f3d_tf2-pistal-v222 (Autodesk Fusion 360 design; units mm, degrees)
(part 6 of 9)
remove_instance "RemoveInstance27"
move_face "MoveFace158"
move "Move73"
delete_face "DeleteFace95"
move_face "MoveFace159"
move "Move74"
move_face "MoveFace160"
move_face "MoveFace161"
fillet "Fillet136" radius 0.5
move_face "MoveFace162"
chamfer "Chamfer42" distance 12.29
chamfer "Chamfer43" distance 2
chamfer "Chamfer44" distance 2.82
fillet "Fillet137" radius 6.5
extrude "Extrude116" new body of existing geometry blind 18.009
combine "Combine96"
fillet "Fillet138" radius 2.5
fillet "Fillet139" radius 1.75
move_face "MoveFace163"
delete_face "DeleteFace96"
delete_face "DeleteFace97"
delete_face "DeleteFace98"
delete_face "DeleteFace99"
move_face "MoveFace164"
move "Move75"
move_face "MoveFace165"
split "Split44" bodies "Prime_L"
split "Split45" bodies "Prime_top Plate"
move_face "MoveFace166"
delete_face "DeleteFace100"
move_face "MoveFace167" TranslateX 0 TranslateY 0 TranslateZ 1.8
move_face "MoveFace168" TranslateX 0 TranslateY 0 TranslateZ 2
move_face "MoveFace169" TranslateX 0 TranslateY 0 TranslateZ 1
sketch "Sketch117" plane through (0, 14.0955, 0) normal (0, -1, 0) x axis (1, 0, 0)
  curve K1 (-5.7369, 17.551) -> (-5.7369, 17.551)
  circle C1 centre (0, 13.7351) radius 13.2351
  circle C2 centre (0.0126, 17.5506) radius 5.7491
split "Split46" bodies "Trigger Gard_Barrel"
remove_body "RemoveBody61"
delete_face "DeleteFace101"
extrude "Extrude117" cut of existing geometry blind -5
chamfer "Chamfer45" distance 2
chamfer "Chamfer46" distance 1
fillet "Fillet140" radius 44.5
fillet "Fillet141" radius 19
move_face "MoveFace170" TranslateX 0 TranslateY -1 TranslateZ 0
fillet "Fillet142" radius 0.4
fillet "Fillet143" radius 1.5
delete_face "DeleteFace102"
chamfer "Chamfer47" distance 1
chamfer "Chamfer48" distance 1
chamfer "Chamfer49" distance 1
move "Move76" TranslateX 0 TranslateY 0 TranslateZ 4
move_face "MoveFace171" TranslateX 0 TranslateY 0 TranslateZ 4
move_face "MoveFace172" TranslateX 0 TranslateY 0 TranslateZ 4
move_face "MoveFace173" TranslateX 0 TranslateY 0 TranslateZ 1.708
move_face "MoveFace174" TranslateX 0 TranslateY 0 TranslateZ 1.708
sketch "Sketch118" plane through (0, 19.0955, 0) normal (0, -1, 0) x axis (1, 0, 0)
  line L1 (-1.9973, 28) -> (1.9977, 28)
  line L2 (-17.9973, -3.324) -> (-17.9973, 12)
  line L3 (17.9977, -3.324) -> (-17.9973, -3.324)
  line L4 (17.9977, 12) -> (17.9977, -3.324)
  circle C1 centre (0.0126, 17.5506) radius 5.7491
  arc A1 centre (1.9977, 12) radius 16 clockwise from (1.9977, 28) to (17.9977, 12)
  arc A2 centre (-1.9973, 12) radius 16 clockwise from (-17.9973, 12) to (-1.9973, 28)
  circle C2 centre (0.0126, 17.5506) radius 7
  concentric C1 C2
  dimension "d994" diameter C2 = 14
split "Split47"
remove_body "RemoveBody62"
move_face "MoveFace175" TranslateX 0 TranslateY 0 TranslateZ -1
sketch "Sketch119" plane through (0, 19.0955, 0) normal (0, -1, 0) x axis (1, 0, 0)
  line L1 (-1.9973, 28) -> (1.9977, 28)
  line L2 (-17.9973, -3.324) -> (-17.9973, 12)
  line L3 (17.9977, -3.324) -> (-17.9973, -3.324)
  line L4 (17.9977, 12) -> (17.9977, -3.324)
  circle C1 centre (0.0126, 17.5506) radius 7
  arc A1 centre (1.9977, 12) radius 16 clockwise from (1.9977, 28) to (17.9977, 12)
  arc A2 centre (-1.9973, 12) radius 16 clockwise from (-17.9973, 12) to (-1.9973, 28)
  circle C2 centre (0.0126, 17.5506) radius 7
  circle C3 centre (0.0126, 17.5506) radius 10
  concentric C1 C2
  concentric C1 C3
  dimension "d998" diameter C3 = 20
extrude "Extrude118" add sketch "Sketch119" profile of C1 C2 C3 along normal blind 3
chamfer "Chamfer50" distance 2
chamfer "Chamfer51" distance 2
chamfer "Chamfer52" distance 3
chamfer "Chamfer53" distance 5
chamfer "Chamfer54" distance 9
chamfer "Chamfer55" distance 15
chamfer "Chamfer56" distance 25
move "Move77"
move_face "MoveFace176" TranslateX 0 TranslateY -1 TranslateZ 0
offset_faces "OffsetFaces11" distance 3.9
offset_faces "OffsetFaces12" distance -4
delete_face "DeleteFace103"
offset_faces "OffsetFaces13" distance -1.5
move_face "MoveFace177" TranslateX 0 TranslateY 0.9 TranslateZ 0
delete_face "DeleteFace104"
move_face "MoveFace178" TranslateX 0 TranslateY 1 TranslateZ 0
fillet "Fillet144" radius 0.5
move "Move78" TranslateX 0 TranslateY 0 TranslateZ 3
move "Move79"
fillet "Fillet145" radius 1
fillet "Fillet146" radius 5
fillet "Fillet147" radius 1
fillet "Fillet148" radius 1
sketch "Sketch120" plane through (-8.7048, 0, 0) normal (-1, 0, 0) x axis (0, -1, 0)
  line L1 (-243.8387, -10.9055) -> (-247.6684, -10.9055)
  line L2 (-240.3387, -15.9055) -> (-240.3387, -14.4055)
  line L3 (-221.9771, -19.4038) -> (-243.7277, -19.4038)
  line L4 (-218.4255, -25.6041) -> (-218.1133, -24.439)
  line L5 (-212.2404, -31.8982) -> (-213.5959, -31.8982)
  line L6 (-211.0185, -30.2363) -> (-211.277, -31.166)
  line L7 (-212.1595, -28.1797) -> (-211.21, -29.3328)
  line L8 (-211.3292, -23.5455) -> (-212.352, -27.2799)
  line L9 (-247.6613, -10.9038) -> (-220.9739, -10.9038)
  line L10 (-219.0873, -25.0216) -> (-211.3818, -27.0863)
  circle C1 centre (-234, -15) radius 2
  arc A1 centre (-247.6684, -14.4055) radius 3.5 clockwise from (-248.5086, -11.0079) to (-247.6684, -10.9055)
  arc A2 centre (-243.8387, -14.4055) radius 3.5 clockwise from (-243.8387, -10.9055) to (-240.3387, -14.4055)
  arc A3 centre (-243.8387, -15.9055) radius 3.5 clockwise from (-240.3387, -15.9055) to (-243.7277, -19.4038)
  arc A4 centre (-221.9771, -23.4038) radius 4 clockwise from (-221.9771, -19.4038) to (-218.1133, -24.439)
  arc A5 centre (-213.5959, -26.8982) radius 5 clockwise from (-213.5959, -31.8982) to (-218.4255, -25.6041)
  arc A6 centre (-212.2404, -30.8982) radius 1 clockwise from (-211.277, -31.166) to (-212.2404, -31.8982)
  arc A7 centre (-211.982, -29.9685) radius 1 clockwise from (-211.21, -29.3328) to (-211.0185, -30.2363)
  arc A8 centre (-211.3876, -27.5441) radius 1 clockwise from (-212.1595, -28.1797) to (-212.352, -27.2799)
  arc A9 centre (-220.9739, -20.9038) radius 10 clockwise from (-220.9739, -10.9038) to (-211.3292, -23.5455)
  arc A10 centre (-247.6613, -14.4038) radius 3.5 clockwise from (-248.5086, -11.0079) to (-247.6613, -10.9038)
  perpendicular L4 L10
split "Split48" bodies "Mag Release_R (1)", "Mag Release_R (2)", "Mag Release_L (1)", "Mag Release_L (2)"
move "Move80"
fillet "Fillet149" radius 6.5
fillet "Fillet150" radius 5.75
combine "Combine97" bodies "Mag Release_R (2)", "Mag Release_R (1)"
combine "Combine98" bodies "Mag Release_L (2)", "Mag Release_L (1)"
fillet "Fillet151" radius 2
move_face "MoveFace179"
move_face "MoveFace180"
sketch "Sketch121" plane through (0, 144.3129, 0) normal (0, -1, 0) x axis (1, 0, 0)
  line L1 (-18.3981, 10) -> (-18.3981, -29.6952)
  line L2 (-19.9977, 10) -> (-18.3981, 10)
  line L3 (-19.9977, -29.2452) -> (-19.9977, 10)
  line L4 (-19.5477, -29.6952) -> (-19.9977, -29.2452)
  line L5 (-18.3981, -29.6952) -> (-19.5477, -29.6952)
  line L6 (18.3981, -29.6952) -> (18.3981, 10)
  line L7 (19.5477, -29.6952) -> (18.3981, -29.6952)
  line L8 (19.9977, -29.2452) -> (19.5477, -29.6952)
  line L9 (19.9977, 10) -> (19.9977, -29.2452)
  line L10 (18.3981, 10) -> (19.9977, 10)
  line L11 (19.9977, -7.3976) -> (-19.9977, -7.3976)
  point P12 (-19.9977, -7.3976)
  point P13 (19.9977, -7.3976)
  coincident L3 P12
  coincident L9 P13
  perpendicular L9 L11
extrude "Extrude119" new body sketch "Sketch121" profile of L1 L3 L4 L5 L6 L7 L8 L9 L11 along normal blind 40
split "Split49" bodies "Trigger Gard_Barrel (1)"
split "Split50" bodies "Trigger Gard_Barrel (3)", "Trigger Gard_Barrel (4)"
combine "Combine99" bodies "Trigger Gard_Barrel (4)"
move_face "MoveFace181"
move_face "MoveFace182"
combine "Combine100"
combine "Combine101" bodies "Trigger Gard_Barrel (3)"
combine "Combine102" bodies "Trigger Gard_Barrel (1)"
extrude "Extrude120" cut of existing geometry blind -0.2
delete_face "DeleteFace105"
delete_face "DeleteFace106"
delete_face "DeleteFace107"
extrude "Extrude121" cut of existing geometry blind -0.2
delete_face "DeleteFace108"
remove_body "RemoveBody63"
remove_body "RemoveBody64"
sketch "Sketch122" plane through (19.9977, 0, 0) normal (1, 0, 0) x axis (0, 1, 0)
  line L1 (104.3129, 10) -> (222.2172, 10)
  line L2 (104.3129, -22.5858) -> (104.3129, 10)
  line L3 (108.2868, -22.5858) -> (104.3129, -22.5858)
  curve K1 (108.2868, -22.5858) -> (115.5438, -25)
  line L4 (121.2561, -25) -> (115.5438, -25)
  curve K2 (140.7874, -29.2452) -> (121.2561, -25)
  line L5 (210.1841, -29.2452) -> (140.7874, -29.2452)
  line L6 (227.5887, -72.0555) -> (210.1841, -29.2452)
  curve K3 (227.8766, -72.7728) -> (227.5887, -72.0555)
  line L7 (240.0468, -84.669) -> (227.8766, -72.7728)
  curve K4 (225.9553, -60.3717) -> (240.0468, -84.669)
  curve K5 (222.2172, -48.7291) -> (225.9553, -60.3717)
  line L8 (222.2172, 10) -> (222.2172, -48.7291)
  line L9 (110, -21) -> (120, -21)
  line L10 (110, -11) -> (110, -21)
  line L11 (120, -11) -> (110, -11)
  line L12 (120, -21) -> (120, -11)
  line L13 (110, -11) -> (120, -21)
  line L14 (120, -11) -> (110, -21)
  point P19 (115, -16)
  horizontal L9
  perpendicular L9 L10
  parallel L9 L11
  parallel L10 L12
  coincident L13 P19
  coincident L14 P19
extrude "Extrude122" cut sketch "Sketch122" profile of L9 L10 L11 L12 against normal blind 70
chamfer "Chamfer57" distance 1
chamfer "Chamfer58" distance 0.5
chamfer "Chamfer59" distance 1
delete_face "DeleteFace109"
chamfer "Chamfer60" distance 0.5
sketch "Sketch123" plane through (-19.9973, 0, 0) normal (-1, 0, 0) x axis (0, -1, 0)
  line L1 (-143.2629, 10) -> (-104.3129, 10)
  line L2 (-143.2629, -29.2452) -> (-143.2629, 10)
  line L3 (-140.7874, -29.2452) -> (-143.2629, -29.2452)
  curve K1 (-140.3243, -28.9762) -> (-140.7874, -29.2452)
  line L4 (-137.502, -28.9762) -> (-140.3243, -28.9762)
  curve K2 (-137.502, -28.9762) -> (-136.5854, -28.7537)
  curve K3 (-136.5854, -28.7537) -> (-123.6009, -24.9502)
  curve K4 (-123.6009, -24.9502) -> (-113.9615, -24.9317)
  curve K5 (-113.9615, -24.9317) -> (-108.2868, -22.5858)
  line L5 (-104.3129, -22.5858) -> (-108.2868, -22.5858)
  line L6 (-104.3129, 10) -> (-104.3129, -22.5858)
  line L7 (-109.5, -20.2071) -> (-109.5, -11.7929)
  line L8 (-110.7929, -21.5) -> (-109.5, -20.2071)
  line L9 (-119.2071, -21.5) -> (-110.7929, -21.5)
  line L10 (-120.5, -20.2071) -> (-119.2071, -21.5)
  line L11 (-120.5, -11.7929) -> (-120.5, -20.2071)
  line L12 (-119.2071, -10.5) -> (-120.5, -11.7929)
  line L13 (-110.7929, -10.5) -> (-119.2071, -10.5)
  line L14 (-109.5, -11.7929) -> (-110.7929, -10.5)
  line L15 (-119, -11) -> (-111, -11)
  line L16 (-110.2929, -11) -> (-119, -11)
  line L17 (-111, -11) -> (-110.2929, -11)
  line L18 (-120, -12) -> (-120, -20)
  line L19 (-120, -20) -> (-120, -12)
  line L20 (-110, -20) -> (-110, -12)
  line L21 (-110, -12) -> (-110, -20)
  line L22 (-119, -21) -> (-111, -21)
  line L23 (-111, -21) -> (-119, -21)
  line L24 (-115, -21) -> (-115, -11)
  line L25 (-110, -16) -> (-120, -16)
  line L26 (-119.9, -11.1) -> (-110.1, -11.1)
  line L27 (-119.9, -20.9) -> (-119.9, -11.1)
  line L28 (-110.1, -20.9) -> (-119.9, -20.9)
  line L29 (-110.1, -11.1) -> (-110.1, -20.9)
  line L30 (-119.9, -20.9) -> (-110.1, -11.1)
  line L31 (-110.1, -20.9) -> (-119.9, -11.1)
  point P30 (-115, -11)
  point P31 (-115, -21)
  point P32 (-120, -16)
  point P33 (-110, -16)
  point P38 (-115, -16)
  point P36 (-119.9, -20.9)
  point P37 (-110.1, -20.9)
  point P35 (-119.9, -11.1)
  midpoint L15 P30
  midpoint L22 P31
  midpoint L19 P32
  midpoint L21 P33
  horizontal L26
  perpendicular L26 L27
  parallel L26 L28
  parallel L27 L29
  coincident L30 P38
  coincident L31 P38
  midpoint L24 P38
  dimension "d1051" distance P36 P37 = 9.8
  dimension "d1052" distance P35 P36 = 9.8
extrude "Extrude123" new body sketch "Sketch123" profile of L8 L10 L12 L14 L24 L25 L26 L27 L28 L29 against normal blind 39.995 bodies "LockPin"
move_face "MoveFace183"
chamfer "Chamfer61" distance 0.5
chamfer "Chamfer62" distance 0.5
move_face "MoveFace184"
move_face "MoveFace185"
move_face "MoveFace186"
chamfer "Chamfer63" distance 0.5
fillet "Fillet152" radius 0.5
fillet "Fillet153" radius 3.5
move_face "MoveFace187"
sketch "Sketch124" plane through (0, 0, 10) normal (0, 0, 1) x axis (-1, 0, 0)
  line L1 (17.9977, -157.3502) -> (17.9977, -232.6902)
  line L2 (13, -157.3502) -> (17.9977, -157.3502)
  line L3 (13, -215.8866) -> (13, -157.3502)
  line L4 (9.005, -215.8866) -> (13, -215.8866)
  line L5 (9.005, -227) -> (9.005, -215.8866)
  line L6 (9.0048, -227) -> (9.005, -227)
  line L7 (9.0048, -233.7413) -> (9.0048, -227)
  line L8 (17.6992, -233.7413) -> (9.0048, -233.7413)
  line L9 (-9.0048, -233.7413) -> (-17.6992, -233.7413)
  line L10 (-9.0048, -227) -> (-9.0048, -233.7413)
  line L11 (-9.005, -227) -> (-9.0048, -227)
  line L12 (-9.005, -215.8866) -> (-9.005, -227)
  line L13 (-13, -215.8866) -> (-9.005, -215.8866)
  line L14 (-13, -157.3502) -> (-13, -215.8866)
  line L15 (-17.9977, -157.3502) -> (-13, -157.3502)
  line L16 (-17.9977, -232.6902) -> (-17.9977, -157.3502)
  line L17 (-17.9977, -215.8866) -> (-13, -215.8866)
  line L18 (17.9977, -215.8866) -> (13, -215.8866)
  arc A1 centre (-453.519, -99.3783) radius 490 clockwise from (17.9977, -232.6902) to (17.6992, -233.7413)
  arc A2 centre (453.519, -99.3783) radius 490 clockwise from (-17.6992, -233.7413) to (-17.9977, -232.6902)
  point P19 (-13, -215.8866)
  point P22 (-13, -215.8866)
  point P23 (-17.9977, -215.8866)
  point P7 (13, -215.8866)
  point P24 (13, -215.8866)
  point P25 (17.9977, -215.8866)
  coincident P19 P22
  coincident L16 P23
  perpendicular L16 L17
  coincident P7 P24
  coincident L1 P25
  perpendicular L1 L18
extrude "Extrude124" add sketch "Sketch124" profile of L1 L2 L3 L14 L15 L16 L17 L18 along normal blind 5
sketch "Sketch125" plane through (0, 0, 15) normal (0, 0, 1) x axis (-1, 0, 0)
  line L1 (17.9977, -215.8866) -> (13, -215.8866)
  line L2 (17.9977, -157.3502) -> (17.9977, -215.8866)
  line L3 (13, -157.3502) -> (17.9977, -157.3502)
  line L4 (13, -215.8866) -> (13, -157.3502)
  line L5 (17.9977, -157.3502) -> (17.9977, -215.8866)
  line L6 (-17.9977, -157.3502) -> (-13, -157.3502)
  line L7 (-17.9977, -215.8866) -> (-17.9977, -157.3502)
  line L8 (-13, -215.8866) -> (-17.9977, -215.8866)
  line L9 (-13, -157.3502) -> (-13, -215.8866)
  line L10 (-19.9977, -222.2172) -> (-19.9977, -104.3129)
  line L11 (19.9977, -143.2629) -> (19.9977, -222.2172)
  line L12 (19.9977, -215.8866) -> (-19.9977, -215.8866)
  line L13 (19.9977, -157.3502) -> (-19.9977, -157.3502)
  point P16 (-19.9977, -215.8866)
  point P17 (19.9977, -215.8866)
  point P18 (-19.9977, -157.3502)
  point P19 (19.9977, -157.3502)
  coincident L10 P16
  coincident L11 P17
  perpendicular L11 L12
  coincident L10 P18
  coincident L11 P19
  perpendicular L11 L13
extrude "Extrude125" add sketch "Sketch125" along normal blind 2
delete_face "DeleteFace110"
delete_face "DeleteFace111"
delete_face "DeleteFace112"
delete_face "DeleteFace113"
move_face "MoveFace188"
sketch "Sketch126" plane through (0, 0, 29) normal (0, 0, 1) x axis (-1, 0, 0)
  line L1 (-9.7981, -202.6682) -> (-9.7981, -70.258)
  line L2 (9.7981, -202.6682) -> (-9.7981, -202.6682)
  line L3 (9.7981, -70.258) -> (9.7981, -202.6682)
  line L4 (-9.7981, -70.258) -> (9.7981, -70.258)
  line L5 (13, -116) -> (-13, -116)
  line L6 (13, -128) -> (13, -116)
  line L7 (-13, -128) -> (13, -128)
  line L8 (-13, -116) -> (-13, -128)
  line L9 (13, -141) -> (-13, -141)
  line L10 (13, -153) -> (13, -141)
  line L11 (-13, -153) -> (13, -153)
  line L12 (-13, -141) -> (-13, -153)
  line L13 (13, -166) -> (-13, -166)
  line L14 (13, -178) -> (13, -166)
  line L15 (-13, -178) -> (13, -178)
  line L16 (-13, -166) -> (-13, -178)
  line L17 (13, -91) -> (-13, -91)
  line L18 (13, -103) -> (13, -91)
  line L19 (-13, -103) -> (13, -103)
  line L20 (-13, -91) -> (-13, -103)
  line L21 (13, -191) -> (-13, -191)
  line L22 (13, -203) -> (13, -191)
  line L23 (-13, -203) -> (13, -203)
  line L24 (-13, -191) -> (-13, -203)
  point P6 (-13, -116)
  point P9 (-13, -128)
  point P10 (-13, -141)
  point P13 (-13, -153)
  point P14 (-13, -166)
  point P17 (-13, -178)
  point P18 (-13, -91)
  point P19 (13, -91)
  point P21 (-13, -103)
  point P22 (-13, -191)
  point P25 (-13, -203)
  horizontal L5
  vertical L6
  horizontal L7
  vertical L8
  horizontal L9
  vertical L10
  horizontal L11
  vertical L12
  horizontal L13
  vertical L14
  horizontal L15
  vertical L16
  horizontal L17
  vertical L18
  horizontal L19
  vertical L20
  horizontal L21
  vertical L22
  horizontal L23
  vertical L24
  dimension "d1066" distance P6 P9 = 12
  dimension "d1067" distance P10 P13 = 12
  dimension "d1068" distance P14 P17 = 12
  dimension "d1069" distance L7 L9 = 13
  dimension "d1070" distance L11 L13 = 13
  dimension "d1071" distance P18 P19 = 26
  dimension "d1072" distance P18 P21 = 12
  dimension "d1073" distance L5 L19 = 13
  dimension "d1074" distance P22 P25 = 12
  dimension "d1075" distance L15 L21 = 13
extrude "Extrude126" new body sketch "Sketch126" profile of L1 L2 L3 L5 L6 L7 L8 L9 L10 L11 L12 L13 L14 L15 L16 L17 L18 L19 L20 L21 L22 L23 L24 against normal blind 2.7
combine "Combine103"
combine "Combine104"
combine "Combine105"
move_face "MoveFace189"
move_face "MoveFace190"
move_face "MoveFace191"
move_face "MoveFace192"
split "Split51" bodies "Prime_R (1)", "Prime_R (2)", "Prime_R (3)", "Prime_R (4)", "Prime_R (5)", "Prime_L (1)", "Prime_L (2)", "Prime_L (3)"
remove_body "RemoveBody65"
remove_body "RemoveBody66"
remove_body "RemoveBody67"
remove_body "RemoveBody68"
remove_body "RemoveBody69"
remove_body "RemoveBody70"
remove_body "RemoveBody71"
remove_body "RemoveBody72"
remove_body "RemoveBody73"
remove_body "RemoveBody74"
remove_body "RemoveBody75"
remove_body "RemoveBody76"
sketch "Sketch127" plane through (0, 202.6683, 0) normal (0, 1, 0) x axis (-1, 0, 0)
  line L1 (12.9294, 26.3) -> (-12.9297, 26.3)
  line L2 (-7.9137, 29) -> (7.9134, 29)
  line L3 (-12.9297, 26.3) -> (12.9294, 26.3)
  line L4 (-9.7981, 22.3) -> (-9.7981, 26.1)
  line L5 (9.7981, 26.1) -> (9.7981, 22.3)
  curve K1 (-4.7222, 26.5873) -> (-8.019, 24.6694)
  curve K2 (8.019, 24.6694) -> (4.7222, 26.5873)
  line L6 (-9.104, 22.8662) -> (-9.7981, 22.8662)
  line L7 (-9.7981, 26.3) -> (-9.7981, 26.1)
  line L8 (9.104, 22.8662) -> (9.7981, 22.8662)
  line L9 (9.7981, 26.3) -> (9.7981, 26.1)
  arc A1 centre (-1.9977, 12) radius 18 clockwise from (-12.9297, 26.3) to (-7.9137, 29)
  arc A2 centre (1.9973, 12) radius 18 clockwise from (7.9134, 29) to (12.9294, 26.3)
  closed curve K3 centre (3.5, 20.7227)
  closed curve K4 centre (-3.5, 20.7227)
  arc A3 centre (-3.5, 20.7227) radius 6.2 clockwise from (-9.3189, 22.8629) to (-6.2082, 26.3)
  arc A4 centre (3.5, 20.7227) radius 6.2 clockwise from (1.8918, 26.7105) to (6.2082, 26.3)
  arc A5 centre (3.5, 20.7227) radius 6.2 clockwise from (6.2082, 26.3) to (9.3177, 22.8662)
  point P22 (-9.7981, 22.8662)
  point P23 (-9.104, 22.8662)
  point P10 (-9.7981, 26.1)
  point P24 (-9.7981, 26.1)
  point P25 (-9.7981, 26.3)
  point P26 (9.7981, 22.8662)
  point P27 (9.104, 22.8662)
  point P13 (9.7981, 26.1)
  point P28 (9.7981, 26.1)
  point P29 (9.7981, 26.3)
  point P31 (-6.2082, 26.3)
  point P19 (-3.5, 20.7227)
  point P30 (-3.5, 20.7227)
  point P34 (6.2082, 26.3)
  point P16 (3.5, 20.7227)
  point P33 (3.5, 20.7227)
  point P37 (9.3177, 22.8662)
  point P36 (3.5, 20.7227)
  coincident L4 P22
  coincident K4 P23
  perpendicular L4 L6
  coincident P10 P24
  coincident L3 P25
  perpendicular L3 L7
  coincident L5 P26
  coincident K3 P27
  perpendicular L5 L8
  coincident P13 P28
  coincident L3 P29
  perpendicular L3 L9
  coincident L3 P31
  coincident P19 P30
  coincident L3 P34
  coincident P16 P33
  coincident L8 P37
  coincident P16 P36
  dimension "d1078" radius A3 = 6.2
  dimension "d1079" radius A4 = 6.2
extrude "Extrude127" new body sketch "Sketch127" profile of L1 L3 L4 L5 L6 L7 L8 L9 A3 A5 against normal blind 132.41
combine "Combine106"
move_face "MoveFace193"
sketch "Sketch128" plane through (0, 70.058, 0) normal (0, 1, 0) x axis (-1, 0, 0)
  line L1 (8.4524, 1) -> (8.4524, 26)
  line L2 (15.2981, 1) -> (8.4524, 1)
  line L3 (15.2981, -14.4738) -> (15.2981, 1)
  line L4 (-7.5981, -22.1738) -> (7.5981, -22.1738)
  line L5 (-15.2981, 1) -> (-15.2981, -14.4738)
  line L6 (-8.4524, 1) -> (-15.2981, 1)
  line L7 (-8.4524, 26) -> (-8.4524, 1)
  line L8 (8.4524, 26) -> (-8.4524, 26)
  line L9 (-19.9977, 10) -> (-19.9977, 12)
  line L10 (-18.3981, 10) -> (-19.9977, 10)
  line L11 (-18.3981, 1) -> (-18.3981, 10)
  line L12 (-15.4981, 1) -> (-18.3981, 1)
  line L13 (-15.4981, -24.564) -> (-15.4981, 1)
  line L14 (-15.4981, -24.564) -> (15.4981, -24.564)
  line L15 (15.4981, 1) -> (15.4981, -24.564)
  line L16 (18.3981, 1) -> (15.4981, 1)
  line L17 (18.3981, 10) -> (18.3981, 1)
  line L18 (19.9973, 10) -> (18.3981, 10)
  line L19 (19.9973, 12) -> (19.9973, 10)
  line L20 (-1.9977, 30) -> (1.9973, 30)
  line L21 (-17.9977, 14) -> (-17.9977, 10)
  line L22 (-17.9977, 10) -> (-17.9977, 14)
  line L23 (-17.9977, 14) -> (-19.9977, 14)
  line L24 (-19.9977, 14) -> (-17.9977, 14)
  line L25 (-19.9977, 10) -> (-19.9973, 10)
  line L26 (-17.9977, 10) -> (-19.9973, 10)
  line L27 (-18.3981, 10) -> (-17.9977, 10)
  line L28 (-19.9977, 10) -> (-18.3981, 10)
  line L29 (17.9977, 14) -> (17.9977, 10)
  line L30 (17.9977, 10) -> (17.9977, 14)
  line L31 (17.9977, 10) -> (18.3981, 10)
  line L32 (19.9973, 10) -> (17.9977, 10)
  line L33 (19.9977, 10) -> (19.9973, 10)
  line L34 (19.9973, 10) -> (19.9977, 10)
  line L35 (18.3981, 10) -> (19.9973, 10)
  line L36 (19.9977, 14) -> (17.9977, 14)
  line L37 (17.9977, 14) -> (19.9977, 14)
  arc A1 centre (7.5981, -14.4738) radius 7.7 clockwise from (15.2981, -14.4738) to (7.5981, -22.1738)
  arc A2 centre (-7.5981, -14.4738) radius 7.7 clockwise from (-7.5981, -22.1738) to (-15.2981, -14.4738)
  arc A3 centre (-1.9977, 12) radius 18 clockwise from (-19.9977, 12) to (-1.9977, 30)
  arc A4 centre (1.9973, 12) radius 18 clockwise from (1.9973, 30) to (19.9973, 12)
extrude "Extrude128" cut sketch "Sketch128" profile of A3 L9 L10 L18 L19 A4 L21 L22 L23 L24 L25 L26 L27 L28 L29 L30 L31 L32 L35 L36 L37 against normal blind 63
sketch "Sketch129" plane through (0, 19.0955, 0) normal (0, -1, 0) x axis (1, 0, 0)
  line L1 (22.3197, 8.4101) -> (20.7973, 8.4101)
  line L2 (22.3197, 12) -> (22.3197, 8.4101)
  line L3 (-1.9973, 32.3224) -> (1.9973, 32.3224)
  line L4 (-22.3197, 8.4101) -> (-22.3197, 12)
  line L5 (-20.7973, 8.4101) -> (-22.3197, 8.4101)
  line L6 (-20.7973, 12) -> (-20.7973, 8.4101)
  line L7 (1.9973, 30.8) -> (-1.9973, 30.8)
  line L8 (20.7973, 8.4101) -> (20.7973, 12)
  line L9 (-18.167, 14) -> (-19.5911, 14)
  line L10 (-17.9977, 12) -> (-17.9977, 14)
  line L11 (-19.7044, 10) -> (-18.3981, 10)
  line L12 (-17.9977, 10) -> (-17.9977, 12)
  line L13 (-17.9977, 10) -> (-18.2902, 10)
  line L14 (-18.3981, 10) -> (-18.2902, 10)
  line L15 (-17.9977, 14) -> (-18.167, 14)
  line L16 (19.5915, 14) -> (18.1673, 14)
  line L17 (18.1673, 14) -> (17.9977, 14)
  line L18 (17.9977, 14) -> (17.9977, 12)
  line L19 (19.8862, 14) -> (19.5915, 14)
  line L20 (17.9977, 14) -> (19.9977, 14)
  line L21 (17.9977, 12) -> (17.9977, 10)
  line L22 (18.2906, 10) -> (17.9977, 10)
  line L23 (18.3981, 10) -> (19.7048, 10)
  line L24 (18.2906, 10) -> (18.3981, 10)
  line L25 (19.9977, 10) -> (19.7048, 10)
  line L26 (-19.5911, 14) -> (-19.8859, 14)
  line L27 (-17.9977, 14) -> (-19.9977, 14)
  line L28 (-21.0977, 13.8) -> (-18.1977, 13.8)
  line L29 (-21.0977, 10.2) -> (-21.0977, 13.8)
  line L30 (-18.1977, 10.2) -> (-21.0977, 10.2)
  line L31 (-18.1977, 13.8) -> (-18.1977, 10.2)
  line L32 (21.0977, 13.8) -> (18.1977, 13.8)
  line L33 (21.0977, 10.2) -> (21.0977, 13.8)
  line L34 (18.1977, 10.2) -> (21.0977, 10.2)
  line L35 (18.1977, 13.8) -> (18.1977, 10.2)
  arc A1 centre (1.9973, 12) radius 20.3224 clockwise from (1.9973, 32.3224) to (22.3197, 12)
  arc A2 centre (-1.9973, 12) radius 20.3224 clockwise from (-22.3197, 12) to (-1.9973, 32.3224)
  arc A3 centre (-1.9973, 12) radius 18.8 clockwise from (-20.7973, 12) to (-1.9973, 30.8)
  arc A4 centre (1.9973, 12) radius 18.8 clockwise from (1.9973, 30.8) to (20.7973, 12)
  horizontal L28
  vertical L29
  horizontal L30
  vertical L31
  horizontal L32
  vertical L33
  horizontal L34
  vertical L35
  dimension "d1084" distance L20 L32 = 0.2
  dimension "d1085" distance L18 L35 = 0.2
  dimension "d1086" distance L22 L34 = 0.2
  dimension "d1087" distance L11 L30 = 0.2
  dimension "d1088" distance L15 L28 = 0.2
  dimension "d1089" distance L10 L31 = 0.2
extrude "Extrude129" new body sketch "Sketch129" profile of L6 A3 A4 L8 L28 L29 L30 L31 L32 L33 L34 L35 against normal blind 204.791
combine "Combine107"
fillet "Fillet154" radius 0.5
move_face "MoveFace194"
move_face "MoveFace195"
sketch "Sketch130" plane through (-18.1977, 0, 0) normal (1, 0, 0) x axis (0, 1, 0)
  line L1 (19.5955, 13.3) -> (228.793, 13.3)
  line L2 (19.5955, 10.7) -> (19.5955, 13.3)
  line L3 (230.6743, 10.7) -> (19.5955, 10.7)
  line L4 (228.793, 13.3) -> (230.6743, 10.7)
  line L5 (227, 10) -> (233.7413, 10)
  line L6 (227, 10) -> (215.8866, 10)
  line L7 (223.8866, 10) -> (223.8866, 17)
  curve K1 (202.6682, 30.2953) -> (228.4312, 13.8)
  line L8 (228.4312, 13.8) -> (228.793, 13.3)
  line L9 (230.6743, 10.7) -> (228.793, 13.3)
  line L10 (230.6743, 10.7) -> (231.0361, 10.2)
  line L11 (226.1158, 17) -> (223.8866, 17)
  line L12 (231.1808, 10) -> (231.0361, 10.2)
  line L13 (224, 10) -> (224, 17)
  point P10 (223.8866, 17)
  point P18 (223.8866, 17)
  point P19 (226.1158, 17)
  point P17 (231.0361, 10.2)
  point P20 (231.0361, 10.2)
  point P21 (231.1808, 10)
  point P22 (224, 17)
  point P23 (224, 10)
  coincident P10 P18
  coincident K1 P19
  perpendicular L7 L11
  coincident P17 P20
  coincident L5 P21
  parallel L10 L12
  coincident L11 P22
  coincident L6 P23
  perpendicular L6 L13
extrude "Extrude130" new body sketch "Sketch130" profile of L1 L3 L5 L6 K1 L8 L10 L11 L12 L13 along normal blind 40 and against normal blind 4
combine "Combine108"
combine "Combine109"
move_face "MoveFace196"
split "Split52" bodies "GripAft_R (1)", "GripAft_L  (1)"
remove_body "RemoveBody77"
remove_body "RemoveBody78"
fillet "Fillet155" radius 0.2
fillet "Fillet156" radius 1.5
move "Move81"
delete_face "DeleteFace114"
delete_face "DeleteFace115"
move "Move82"
move_face "MoveFace197"
fillet "Fillet157" radius 0.2
delete_face "DeleteFace116"
delete_face "DeleteFace117"
fillet "Fillet158" radius 0.5
fillet "Fillet159" radius 1.25
move_face "MoveFace198"
move_face "MoveFace199"
chamfer "Chamfer64" distance 1
move_face "MoveFace200"
chamfer "Chamfer65" distance 1.314
fillet "Fillet160" radius 28.25
combine "Combine110"
sketch "Sketch131" plane through (0, 146.2975, 39.2504) normal (0, 0.9658, 0.2591) x axis (-1, 0, 0)
  line L1 (-9.9977, -113.0105) -> (-9.9977, -106.1973)
  curve K1 (-4.9977, -118.0121) -> (-9.9977, -113.0105)
  line L2 (4.9977, -118.0121) -> (-4.9977, -118.0121)
  curve K2 (9.9977, -113.0105) -> (4.9977, -118.0121)
  line L3 (9.9977, -106.1973) -> (9.9977, -113.0105)
  line L4 (-7.9977, -104.1972) -> (7.9977, -104.1972)
  line L5 (-5.6, -107.2) -> (5.6, -107.2)
  line L6 (-5.6, -101.1945) -> (-5.6, -107.2)
  line L7 (5.6, -101.1945) -> (-5.6, -101.1945)
  line L8 (5.6, -107.2) -> (5.6, -101.1945)
  line L9 (-5.6, -101.1945) -> (5.6, -107.2)
  line L10 (5.6, -101.1945) -> (-5.6, -107.2)
  closed curve K3 centre (-7.9977, -106.1973)
  closed curve K4 centre (7.9977, -106.1973)
  point P16 (0, -104.1972)
  horizontal L5
  perpendicular L5 L6
  parallel L5 L7
  parallel L6 L8
  coincident L9 P16
  coincident L10 P16
  midpoint L4 P16
extrude "Extrude131" add sketch "Sketch131" profile of L4 L5 L6 L8 along normal blind 2.428
delete_face "DeleteFace118"
delete_face "DeleteFace119"
chamfer "Chamfer66" distance 1.598
delete_face "DeleteFace120"
fillet "Fillet161" radius 2
fillet "Fillet162" radius 2
move_face "MoveFace201"
move_face "MoveFace202"
combine "Combine111"
offset_faces "OffsetFaces14" distance -0.3
delete_face "DeleteFace121"
delete_face "DeleteFace122"
move_face "MoveFace203"
move_face "MoveFace204"
chamfer "Chamfer67" distance 0.3
delete_face "DeleteFace123"
delete_face "DeleteFace124"
delete_face "DeleteFace125"
delete_face "DeleteFace126"
chamfer "Chamfer68" distance 0.5
offset_faces "OffsetFaces15" distance 0.75
sketch "Sketch132" plane through (0, 0, 26.3) normal (0, 0, -1) x axis (1, 0, 0)
  line L1 (-6.2082, -216.6683) -> (-6.2082, -70.2583)
  line L2 (6.2082, -216.6683) -> (-6.2082, -216.6683)
  line L3 (6.2082, -70.2583) -> (6.2082, -216.6683)
  line L4 (9.7981, -70.2583) -> (6.2082, -70.2583)
  line L5 (9.7981, -70.258) -> (9.7981, -70.2583)
  line L6 (-9.7981, -70.258) -> (9.7981, -70.258)
  line L7 (-9.7981, -70.2583) -> (-9.7981, -70.258)
  line L8 (-6.2082, -70.2583) -> (-9.7981, -70.2583)
  circle C1 centre (-0.0006, -177.3741) radius 1.5
  circle C2 centre (0.0406, -189.4201) radius 1.5
  circle C3 centre (0.0406, -189.4201) radius 1.5
  circle C4 centre (0.0406, -189.4201) radius 1.5
extrude "Extrude132" cut sketch "Sketch132" profile of C1 C2 C3 C4 against normal blind 10
chamfer "Chamfer69" distance 1.6
sketch "Sketch133" plane through (12.7981, 0, 0) normal (1, 0, 0) x axis (0, 1, 0)
  line L1 (178.2, 26.3997) -> (190.8, 26.3997)
  line L2 (178.2, 26.1) -> (178.2, 26.3997)
  line L3 (165.8, 26.1) -> (178.2, 26.1)
  line L4 (165.8, 26.3997) -> (165.8, 26.1)
  line L5 (153.2, 26.3997) -> (165.8, 26.3997)
  line L6 (153.2, 26.1) -> (153.2, 26.3997)
  line L7 (140.8, 26.1) -> (153.2, 26.1)
  line L8 (140.8, 26.3997) -> (140.8, 26.1)
  line L9 (128.2, 26.3997) -> (140.8, 26.3997)
  line L10 (128.2, 26.1) -> (128.2, 26.3997)
  line L11 (115.8, 26.1) -> (128.2, 26.1)
  line L12 (115.8, 26.3997) -> (115.8, 26.1)
  line L13 (103.2, 26.3997) -> (115.8, 26.3997)
  line L14 (103.2, 26.1) -> (103.2, 26.3997)
  line L15 (90.8, 26.1) -> (103.2, 26.1)
  line L16 (90.8, 26.3997) -> (90.8, 26.1)
  line L17 (72.258, 26.3997) -> (90.8, 26.3997)
  line L18 (72.258, 2.0244) -> (72.258, 26.3997)
  line L19 (80.1147, 2.0244) -> (72.258, 2.0244)
  line L20 (95.9689, 21.6299) -> (86.6444, 21.5887)
  line L21 (98.2082, 21.6343) -> (96.0036, 21.6343)
  line L22 (99.0393, 20.0686) -> (99.0789, 20.5623)
  curve K1 (100.6801, 14.8028) -> (99.0393, 20.0686)
  curve K2 (104.47, 20.0672) -> (102.8265, 14.8022)
  line L23 (104.4307, 20.5609) -> (104.47, 20.0672)
  line L24 (107.5222, 21.6343) -> (105.3176, 21.6343)
  line L25 (108.3533, 20.0686) -> (108.3929, 20.5623)
  curve K3 (109.9941, 14.8028) -> (108.3533, 20.0686)
  curve K4 (113.784, 20.0672) -> (112.1405, 14.8022)
  line L26 (113.7447, 20.5609) -> (113.784, 20.0672)
  line L27 (116.8362, 21.6343) -> (114.6316, 21.6343)
  line L28 (117.6673, 20.0686) -> (117.7069, 20.5623)
  curve K5 (119.3081, 14.8028) -> (117.6673, 20.0686)
  curve K6 (123.098, 20.0672) -> (121.4545, 14.8022)
  line L29 (123.0587, 20.5609) -> (123.098, 20.0672)
  line L30 (126.1502, 21.6343) -> (123.9456, 21.6343)
  line L31 (126.9813, 20.0686) -> (127.0209, 20.5623)
  curve K7 (128.6221, 14.8028) -> (126.9813, 20.0686)
  curve K8 (132.412, 20.0672) -> (130.7685, 14.8022)
  line L32 (132.3727, 20.5609) -> (132.412, 20.0672)
  line L33 (135.4642, 21.6343) -> (133.2596, 21.6343)
  line L34 (136.2953, 20.0686) -> (136.3349, 20.5623)
  curve K9 (137.9361, 14.8028) -> (136.2953, 20.0686)
  curve K10 (141.726, 20.0672) -> (140.0825, 14.8022)
  line L35 (141.6867, 20.5609) -> (141.726, 20.0672)
  line L36 (144.7782, 21.6343) -> (142.5736, 21.6343)
  line L37 (145.6093, 20.0686) -> (145.6489, 20.5623)
  curve K11 (147.2501, 14.8028) -> (145.6093, 20.0686)
  curve K12 (151.04, 20.0672) -> (149.3965, 14.8022)
  line L38 (151.0007, 20.5609) -> (151.04, 20.0672)
  line L39 (154.0922, 21.6343) -> (151.8876, 21.6343)
  line L40 (154.9233, 20.0686) -> (154.9629, 20.5623)
  curve K13 (156.5641, 14.8028) -> (154.9233, 20.0686)
  curve K14 (160.354, 20.0672) -> (158.7105, 14.8022)
  line L41 (160.3147, 20.5609) -> (160.354, 20.0672)
  line L42 (163.4062, 21.6343) -> (161.2016, 21.6343)
  line L43 (164.2373, 20.0686) -> (164.2769, 20.5623)
  curve K15 (165.8781, 14.8028) -> (164.2373, 20.0686)
  curve K16 (169.668, 20.0672) -> (168.0245, 14.8022)
  line L44 (169.6287, 20.5609) -> (169.668, 20.0672)
  line L45 (172.7202, 21.6343) -> (170.5156, 21.6343)
  line L46 (173.5513, 20.0686) -> (173.5909, 20.5623)
  curve K17 (175.1921, 14.8028) -> (173.5513, 20.0686)
  curve K18 (178.982, 20.0672) -> (177.3385, 14.8022)
  line L47 (178.9427, 20.5609) -> (178.982, 20.0672)
  line L48 (182.0342, 21.6343) -> (179.8296, 21.6343)
  line L49 (182.8653, 20.0686) -> (182.9049, 20.5623)
  curve K19 (184.5061, 14.8028) -> (182.8653, 20.0686)
  curve K20 (188.296, 20.0672) -> (186.6525, 14.8022)
  line L50 (188.2567, 20.5609) -> (188.296, 20.0672)
  line L51 (189.1436, 22.3) -> (188.5441, 21.3452)
  line L52 (216.6682, 22.3) -> (189.1436, 22.3)
  line L53 (216.6682, 26.1) -> (216.6682, 22.3)
  line L54 (190.8, 26.1) -> (216.6682, 26.1)
  line L55 (190.8, 26.3997) -> (190.8, 26.1)
  line L56 (77.1329, 14.212) -> (82.8671, 14.212)
  line L57 (77.1329, 23.788) -> (77.1329, 14.212)
  line L58 (82.8671, 23.788) -> (77.1329, 23.788)
  line L59 (82.8671, 14.212) -> (82.8671, 23.788)
  line L60 (77.1329, 23.788) -> (82.8671, 14.212)
  line L61 (82.8671, 23.788) -> (77.1329, 14.212)
  arc A1 centre (121.5101, -0.9197) radius 41.5 clockwise from (80.1147, 2.0244) to (86.6444, 21.5887)
  arc A2 centre (96.1135, 20.6404) radius 1 clockwise from (95.9689, 21.6299) to (96.0036, 21.6343)
  arc A3 centre (98.0821, 20.6423) radius 1 clockwise from (98.2082, 21.6343) to (99.0789, 20.5623)
  arc A4 centre (101.7635, 53.7877) radius 39 clockwise from (102.8265, 14.8022) to (100.6801, 14.8028)
  arc A5 centre (105.4275, 20.6404) radius 1 clockwise from (104.4307, 20.5609) to (105.3176, 21.6343)
  arc A6 centre (107.3961, 20.6423) radius 1 clockwise from (107.5222, 21.6343) to (108.3929, 20.5623)
  arc A7 centre (111.0775, 53.7877) radius 39 clockwise from (112.1405, 14.8022) to (109.9941, 14.8028)
  arc A8 centre (114.7415, 20.6404) radius 1 clockwise from (113.7447, 20.5609) to (114.6316, 21.6343)
  arc A9 centre (116.7101, 20.6423) radius 1 clockwise from (116.8362, 21.6343) to (117.7069, 20.5623)
  arc A10 centre (120.3915, 53.7877) radius 39 clockwise from (121.4545, 14.8022) to (119.3081, 14.8028)
  arc A11 centre (124.0555, 20.6404) radius 1 clockwise from (123.0587, 20.5609) to (123.9456, 21.6343)
  arc A12 centre (126.0241, 20.6423) radius 1 clockwise from (126.1502, 21.6343) to (127.0209, 20.5623)
  arc A13 centre (129.7055, 53.7877) radius 39 clockwise from (130.7685, 14.8022) to (128.6221, 14.8028)
  arc A14 centre (133.3695, 20.6404) radius 1 clockwise from (132.3727, 20.5609) to (133.2596, 21.6343)
  arc A15 centre (135.3381, 20.6423) radius 1 clockwise from (135.4642, 21.6343) to (136.3349, 20.5623)
  arc A16 centre (139.0195, 53.7877) radius 39 clockwise from (140.0825, 14.8022) to (137.9361, 14.8028)
  arc A17 centre (142.6835, 20.6404) radius 1 clockwise from (141.6867, 20.5609) to (142.5736, 21.6343)
  arc A18 centre (144.6521, 20.6423) radius 1 clockwise from (144.7782, 21.6343) to (145.6489, 20.5623)
  arc A19 centre (148.3335, 53.7877) radius 39 clockwise from (149.3965, 14.8022) to (147.2501, 14.8028)
  arc A20 centre (151.9975, 20.6404) radius 1 clockwise from (151.0007, 20.5609) to (151.8876, 21.6343)
  arc A21 centre (153.9661, 20.6423) radius 1 clockwise from (154.0922, 21.6343) to (154.9629, 20.5623)
  arc A22 centre (157.6475, 53.7877) radius 39 clockwise from (158.7105, 14.8022) to (156.5641, 14.8028)
  arc A23 centre (161.3115, 20.6404) radius 1 clockwise from (160.3147, 20.5609) to (161.2016, 21.6343)
  arc A24 centre (163.2801, 20.6423) radius 1 clockwise from (163.4062, 21.6343) to (164.2769, 20.5623)
  arc A25 centre (166.9615, 53.7877) radius 39 clockwise from (168.0245, 14.8022) to (165.8781, 14.8028)
  arc A26 centre (170.6255, 20.6404) radius 1 clockwise from (169.6287, 20.5609) to (170.5156, 21.6343)
  arc A27 centre (172.5941, 20.6423) radius 1 clockwise from (172.7202, 21.6343) to (173.5909, 20.5623)
  arc A28 centre (176.2755, 53.7877) radius 39 clockwise from (177.3385, 14.8022) to (175.1921, 14.8028)
  arc A29 centre (179.9395, 20.6404) radius 1 clockwise from (178.9427, 20.5609) to (179.8296, 21.6343)
  arc A30 centre (181.9081, 20.6423) radius 1 clockwise from (182.0342, 21.6343) to (182.9049, 20.5623)
  arc A31 centre (185.5895, 53.7877) radius 39 clockwise from (186.6525, 14.8022) to (184.5061, 14.8028)
  arc A32 centre (189.2535, 20.6404) radius 1 clockwise from (188.2567, 20.5609) to (188.5441, 21.3452)
  point P145 (80, 19)
  point P141 (82.8671, 14.212)
  horizontal L56
  perpendicular L56 L57
  parallel L56 L58
  parallel L57 L59
  coincident L60 P145
  coincident L61 P145
  coincident A1 P141
extrude "Extrude133" new body sketch "Sketch133" profile of L56 L57 L58 L59 along normal blind 7.062
move "Move83"
move "Move84"
move_face "MoveFace205"
move "Move85"
move_face "MoveFace206"
move_face "MoveFace207"
fillet "Fillet163" radius 1
split "Split53"
remove_body "RemoveBody79"
sketch "Sketch134" plane through (0, 160.0071, 0) normal (0, 1, 0) x axis (-1, 0, 0)
  line L1 (-12.7981, 18.3) -> (-18.8592, 18.3)
  line L2 (-12.7981, 26.1) -> (-12.7981, 18.3)
  line L3 (-13.1865, 26.1) -> (-12.7981, 26.1)
  arc A1 centre (-1.9977, 12) radius 18 clockwise from (-18.8592, 18.3) to (-13.1865, 26.1)
  circle C1 centre (-15.0846, 20.3468) radius 2
  dimension "d1130" diameter C1 = 4
extrude "Extrude134" new body sketch "Sketch134" profile of C1 against normal blind 105.68
mirror "Mirror31" mirrorStitchTolerance 0.1
combine "Combine112"
combine "Combine113"
combine "Combine114"
combine "Combine115"
combine "Combine116"
combine "Combine117"
offset_faces "OffsetFaces16" distance 1
combine "Combine118"
delete_face "DeleteFace127"
sketch "Sketch135" plane through (0, 68.3245, -205.543) normal (0, -0.3154, 0.9489) x axis (1, 0, 0)
  line L1 (19.9973, 206.2016) -> (19.9973, 147.4253)
  curve K1 (19.9973, 206.2016) -> (9.9973, 216.8857)
  line L2 (9.9973, 216.8857) -> (-9.9977, 216.8857)
  curve K2 (-9.9977, 216.8857) -> (-19.9977, 206.2016)
  line L3 (-19.9977, 147.4253) -> (-19.9977, 206.2016)
  line L4 (-18.8981, 147.9253) -> (-19.4977, 147.9253)
  line L5 (-12.5019, 148.4253) -> (-18.3981, 148.4253)
  line L6 (-12.5019, 162.499) -> (-12.5019, 148.4253)
  line L7 (-12.5073, 162.499) -> (-12.5019, 162.499)
  line L8 (-12.5073, 186.986) -> (-12.5073, 162.499)
  line L9 (12.4927, 186.986) -> (-12.5073, 186.986)
  line L10 (12.4927, 162.5113) -> (12.4927, 186.986)
  line L11 (12.4981, 162.5113) -> (12.4927, 162.5113)
  line L12 (12.4981, 148.4253) -> (12.4981, 162.5113)
  line L13 (18.3981, 148.4253) -> (12.4981, 148.4253)
  line L14 (19.4973, 147.9253) -> (18.8981, 147.9253)
  line L15 (12.4927, 186.986) -> (-12.5073, 186.986)
  line L16 (-6, 186.986) -> (6, 186.986)
  line L17 (-6, 205.014) -> (-6, 186.986)
  line L18 (6, 205.014) -> (-6, 205.014)
  line L19 (6, 186.986) -> (6, 205.014)
  line L20 (-6, 205.014) -> (6, 186.986)
  line L21 (6, 205.014) -> (-6, 186.986)
  arc A1 centre (-19.4977, 147.4253) radius 0.5 clockwise from (-19.9977, 147.4253) to (-19.4977, 147.9253)
  arc A2 centre (-18.8981, 148.4253) radius 0.5 clockwise from (-18.3981, 148.4253) to (-18.8981, 147.9253)
  arc A3 centre (18.8981, 148.4253) radius 0.5 clockwise from (18.8981, 147.9253) to (18.3981, 148.4253)
  arc A4 centre (19.4973, 147.4253) radius 0.5 clockwise from (19.4973, 147.9253) to (19.9973, 147.4253)
  point P32 (0, 196)
  point P30 (-6, 205.014)
  point P31 (6, 205.014)
  horizontal L16
  perpendicular L16 L17
  parallel L16 L18
  parallel L17 L19
  coincident L20 P32
  coincident L21 P32
  dimension "d1136" distance P30 P31 = 12
extrude "Extrude135" new body sketch "Sketch135" profile of L9 L15 L16 L17 L18 L19 along normal blind 10
sketch "Sketch136" plane through (6, 0, 0) normal (1, 0, 0) x axis (0, 1, 0)
  line L1 (262.8717, -140.8736) -> (245.7641, -146.5603)
  line L2 (259.7173, -131.3841) -> (262.8717, -140.8736)
  line L3 (242.6097, -137.0709) -> (259.7173, -131.3841)
  line L4 (245.7641, -146.5603) -> (242.6097, -137.0709)
  line L5 (239.9484, -124.9418) -> (240.6628, -127.5974)
  line L6 (248.3803, -156.2854) -> (248.2505, -155.8026)
  line L7 (248.2505, -155.8026) -> (248.3803, -156.2854)
  line L8 (220.3025, -51.9132) -> (248.3803, -156.2854)
  line L9 (248.3803, -156.2854) -> (220.3025, -51.9132)
  line L10 (245.7641, -146.5603) -> (262.8717, -140.8736)
  line L11 (259.7173, -131.3841) -> (242.6097, -137.0709)
  line L12 (259.7173, -131.3841) -> (262.8717, -140.8736)
extrude "Extrude136" new body sketch "Sketch136" profile of L1 L2 L3 L8 L9 L10 L11 L12 along normal blind 6.493
mirror "Mirror32" mirrorStitchTolerance 0.1
combine "Combine119"
move_face "MoveFace208"
move_face "MoveFace209"
combine "Combine120"
move_face "MoveFace210"
combine "Combine121"
combine "Combine122"
combine "Combine123"
combine "Combine124"
combine "Combine125"
move_face "MoveFace211"
move_face "MoveFace212"
move_face "MoveFace213"
sketch "Sketch137" plane through (12.493, 0, 0) normal (1, 0, 0) x axis (0, 1, 0)
  line L1 (245.7641, -146.5603) -> (243.214, -137.0808)
  line L2 (262.6819, -140.9367) -> (245.7641, -146.5603)
  line L3 (259.5906, -131.637) -> (262.6819, -140.9367)
  line L4 (243.214, -137.0808) -> (259.5906, -131.637)
  line L5 (246.144, -139.4331) -> (246, -139)
  line L6 (247.7843, -144.3676) -> (246.144, -139.4331)
  line L7 (252.7188, -142.7274) -> (247.7843, -144.3676)
  line L8 (251.0785, -137.7928) -> (252.7188, -142.7274)
  line L9 (246.144, -139.4331) -> (251.0785, -137.7928)
  point P8 (247.7843, -144.3676)
  point P9 (252.7188, -142.7274)
  point P7 (246.144, -139.4331)
  point P10 (251.0785, -137.7928)
  perpendicular L6 L7
  dimension "d1144" distance P8 P9 = 5.2
  dimension "d1145" distance P7 P8 = 5.2
  dimension "d1146" distance P9 P10 = 5.2
extrude "Extrude137" cut sketch "Sketch137" profile of L6 L7 L8 L9 distance 70
chamfer "Chamfer70" distance 0.5
chamfer "Chamfer71" distance 0.35
delete_face "DeleteFace128"
chamfer "Chamfer72" distance 0.35
delete_face "DeleteFace129"
chamfer "Chamfer73" distance 0.35
sketch "Sketch138" plane through (-21.9977, 0, 0) normal (-1, 0, 0) x axis (0, -1, 0)
  line L1 (-251.5226, -138.0193) -> (-252.4999, -140.9593)
  line L2 (-250.6312, -137.5727) -> (-251.5226, -138.0193)
  line L3 (-246.3705, -138.989) -> (-250.6312, -137.5727)
  line L4 (-245.9238, -139.8804) -> (-246.3705, -138.989)
  line L5 (-246.9532, -142.977) -> (-245.9238, -139.8804)
  line L6 (-202.4935, -157.7558) -> (-246.9532, -142.977)
  line L7 (-197.128, -152.3541) -> (-198.032, -155.4234)
  line L8 (-197.128, -141.3784) -> (-197.128, -152.3541)
  line L9 (-157.1727, -23.4112) -> (-197.128, -141.3784)
  line L10 (-181.4232, -15.4864) -> (-162.8556, -15.4864)
  line L11 (-182.8566, -22.0495) -> (-181.4232, -15.4864)
  line L12 (-220.8838, -26.6905) -> (-188.6207, -26.6905)
  line L13 (-220.8838, -56.1363) -> (-220.8838, -26.6905)
  line L14 (-253.6825, -136.8114) -> (-220.8838, -56.1363)
  line L15 (-246.6184, -139.2754) -> (-250.604, -137.9506)
  line L16 (-247.2853, -142.8666) -> (-246.3017, -139.9076)
  line L17 (-252.2443, -142.8851) -> (-248.2587, -144.2099)
  line L18 (-251.2362, -138.2673) -> (-252.1678, -141.0697)
  line L19 (-252.9192, -143.3302) -> (-252.1678, -141.0697)
  line L20 (-246.6498, -144.7447) -> (-248.2587, -144.2099)
  line L21 (-255.3113, -141.8656) -> (-252.1395, -142.9199)
  line L22 (-250.604, -136.3655) -> (-251.2362, -138.2673)
  line L23 (-252.4383, -137.3408) -> (-250.604, -137.9506)
  line L24 (-244.7858, -139.8846) -> (-246.6184, -139.2754)
  line L25 (-245.6611, -137.9804) -> (-246.3017, -139.9076)
  line L26 (-247.9797, -144.9556) -> (-247.2853, -142.8666)
  circle C1 centre (-210.9636, -95.9994) radius 18.6716
  arc A1 centre (-201.3894, -154.4345) radius 3.5 clockwise from (-198.032, -155.4234) to (-202.4935, -157.7558)
  arc A2 centre (-162.8556, -21.4864) radius 6 clockwise from (-162.8556, -15.4864) to (-157.1727, -23.4112)
  arc A3 centre (-188.6207, -20.7905) radius 5.9 clockwise from (-182.8566, -22.0495) to (-188.6207, -26.6905)
  arc A4 centre (-250.4402, -138.1296) radius 3.5 clockwise from (-252.4999, -140.9593) to (-253.6825, -136.8114)
  point P31 (-252.1678, -141.0697)
  point P33 (-252.1678, -141.0697)
  point P29 (-248.2587, -144.2099)
  point P35 (-248.2587, -144.2099)
  point P37 (-252.1395, -142.9199)
  point P32 (-251.2362, -138.2673)
  point P39 (-251.2362, -138.2673)
  point P25 (-250.604, -137.9506)
  point P41 (-250.604, -137.9506)
  point P26 (-246.6184, -139.2754)
  point P43 (-246.6184, -139.2754)
  point P27 (-246.3017, -139.9076)
  point P45 (-246.3017, -139.9076)
  point P28 (-247.2853, -142.8666)
  point P47 (-247.2853, -142.8666)
  coincident P31 P33
  parallel L18 L19
  coincident P29 P35
  parallel L17 L20
  coincident L17 P37
  perpendicular L19 L21
  coincident P32 P39
  parallel L18 L22
  coincident P25 P41
  parallel L15 L23
  coincident P26 P43
  parallel L15 L24
  coincident P27 P45
  parallel L16 L25
  coincident P28 P47
  perpendicular L15 L26
extrude "Extrude138" new body sketch "Sketch138" profile of L2 L4 L15 L16 L17 L18 L19 L20 L21 L22 L23 L24 L25 L26 against normal blind 43.995 bodies "Handel Pin"
delete_face "DeleteFace130"
delete_face "DeleteFace131"
chamfer "Chamfer74" distance 0.5
move_face "MoveFace214"
move_face "MoveFace215"
move_face "MoveFace216"
move_face "MoveFace217"
sketch "Sketch139" plane through (0, 0, 0) normal (-1, 0, 0) x axis (0, -1, 0)
  line L1 (-243.214, -137.0808) -> (-259.7804, -131.5739)
  line L2 (-225.7243, -72.0674) -> (-243.214, -137.0808)
  line L3 (-220.3025, -51.9132) -> (-225.7243, -72.0674)
  line L4 (-219.9103, -50.4552) -> (-220.3025, -51.9132)
  line L5 (-221, -47) -> (-219.9103, -50.4552)
  line L6 (-228.6991, -19.812) -> (-221, -47)
  line L7 (-249.5886, -19.812) -> (-228.6991, -19.812)
  line L8 (-235.4799, -32.5465) -> (-249.5886, -19.812)
  line L9 (-232.2172, -48.7291) -> (-232.2172, -34.9278)
  curve K1 (-233.7172, -53.9969) -> (-232.2172, -48.7291)
  curve K2 (-234.0863, -54.5504) -> (-233.7172, -53.9969)
  curve K3 (-274.1373, -137.1288) -> (-234.0863, -54.5504)
  line L10 (-262.8717, -140.8736) -> (-274.1373, -137.1288)
  line L11 (-259.7804, -131.5739) -> (-262.8717, -140.8736)
  line L12 (-220.3025, -51.9132) -> (-225.7243, -72.0673)
  line L13 (-225.7243, -72.0673) -> (-243.214, -137.0808)
  line L14 (-219.9103, -50.4552) -> (-220.3025, -51.9132)
  line L15 (-236.1966, -76.2415) -> (-228.7303, -48.4876)
  line L16 (-221.138, -55.0188) -> (-229.8564, -52.6734)
  line L17 (-225.1962, -70.1041) -> (-233.9145, -67.7587)
  line L18 (-225.4972, -49.3573) -> (-228.7303, -48.4876)
  line L19 (-232.0345, -73.6582) -> (-225.4972, -49.3573)
  line L20 (-235.2676, -72.7885) -> (-232.0345, -73.6582)
  line L21 (-230.9458, -56.7232) -> (-225.1962, -70.1041)
  arc A1 centre (-222.4144, -18.0709) radius 19.5 clockwise from (-232.2172, -34.9278) to (-235.4799, -32.5465)
  point P24 (-229.8564, -52.6734)
  point P25 (-221.138, -55.0188)
  point P26 (-233.9145, -67.7587)
  point P27 (-225.1962, -70.1041)
  point P30 (-235.2676, -72.7885)
  point P31 (-230.9458, -56.7232)
  parallel L12 L15
  coincident L15 P24
  coincident L3 P25
  perpendicular L3 L16
  coincident L15 P26
  coincident L12 P27
  perpendicular L12 L17
  perpendicular L15 L18
  perpendicular L17 L19
  coincident L15 P30
  perpendicular L15 L20
  coincident L15 P31
extrude "Extrude139" new body sketch "Sketch139" profile of L3 L12 L15 L16 L18 L19 L21 distance 5
combine "Combine126"
combine "Combine127"
move_face "MoveFace218"
move_face "MoveFace219"
move_face "MoveFace220"
move_face "MoveFace221"
move_face "MoveFace222"
combine "Combine128"
sketch "Sketch140" plane through (-5, 0, 0) normal (-1, 0, 0) x axis (0, -1, 0)
  line L1 (-230.7346, -56.7081) -> (-228.5891, -48.7327)
  line L2 (-225.1123, -69.7925) -> (-230.7346, -56.7081)
  line L3 (-221.1899, -55.212) -> (-225.1123, -69.7925)
  line L4 (-226.8683, -53.6844) -> (-221.1899, -55.212)
  line L5 (-225.7423, -49.4985) -> (-226.8683, -53.6844)
  line L6 (-228.5891, -48.7327) -> (-225.7423, -49.4985)
  line L7 (-174.0918, -64.3446) -> (-202.0712, -168.3511)
  line L8 (-164.4807, -71.7434) -> (-175.2992, -68.833)
  line L9 (-166.1217, -77.8435) -> (-164.4807, -71.7434)
  curve K1 (-104.3129, -80.5778) -> (-103.037, -79.5602)
  curve K2 (-103.037, -79.5602) -> (-75.258, -25.0613)
  curve K3 (-103.037, -79.5602) -> (-75.258, -25.0613)
  curve K4 (-104.3129, -80.5778) -> (-103.037, -79.5602)
  curve K5 (-144.3129, -82.587) -> (-104.3129, -80.5778)
  line L10 (-176.8777, -74.7308) -> (-144.3129, -82.587)
  line L11 (-176.8777, -74.7308) -> (-144.3129, -82.587)
  curve K6 (-144.3129, -82.587) -> (-104.3129, -80.5778)
  line L12 (-165.9909, -77.3572) -> (-176.8777, -74.7308)
  line L13 (-165.9909, -77.3572) -> (-164.4807, -71.7434)
  line L14 (-176.8777, -74.7308) -> (-175.2992, -68.833)
  point P10 (-175.2992, -68.833)
  point P17 (-176.8777, -74.7308)
  point P18 (-176.8777, -74.7308)
  point P19 (-165.9909, -77.3572)
  coincident L7 P10
  perpendicular L7 L8
  perpendicular L8 L9
  coincident P17 P18
  coincident L9 P19
  coincident L10 P19
extrude "Extrude140" new body sketch "Sketch140" profile of L8 L9 L10 L11 L12 L13 L14 against normal blind 10
move "Move86"
move_face "MoveFace223"
combine "Combine129"
move_face "MoveFace224"
move_face "MoveFace225"
move_face "MoveFace226"
move_face "MoveFace227"
combine "Combine130"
